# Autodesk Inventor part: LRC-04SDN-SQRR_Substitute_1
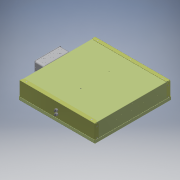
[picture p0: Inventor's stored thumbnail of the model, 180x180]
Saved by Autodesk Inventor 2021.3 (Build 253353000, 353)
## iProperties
Part Number: LRC-04SDN-SQRR_Substitute_1
Material: Generic
Document SubType Name: Modeling
Designer: JChurch
Manufacturer: Standard
Standards Organization: Custom
Density: 1 g/cm^3
Appearance: Smooth - Black
Author: JChurch
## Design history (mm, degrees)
derived "LRC-04SDN-SQRR.iam"
body "Solid9"
node "830557-00-00.iam:1::830557-PAN.ipt:1"
node "830557-00-00.iam:1::830557-FLANGE.ipt:2"
body "Solid10"
node "830557-00-00.iam:1::506010-00-38 SQUEEZED.ipt:1"
body "Solid11"
node "830557-00-00.iam:1::506010-00-38 SQUEEZED.ipt:2"
body "Solid12"
node "830557-00-00.iam:1::506010-00-38 SQUEEZED.ipt:3"
body "Solid13"
node "830557-00-00.iam:1::506010-00-38 SQUEEZED.ipt:4"
body "Solid14"
node "830557-00-00.iam:1::506010-00-38 SQUEEZED.ipt:5"
body "Solid15"
node "830557-00-00.iam:1::506010-00-38 SQUEEZED.ipt:6"
body "Solid16"
node "830557-00-00.iam:1::506010-00-38 SQUEEZED.ipt:7"
body "Solid17"
node "830557-00-00.iam:1::506010-00-38 SQUEEZED.ipt:8"
body "Solid18"
node "830557-00-00.iam:1::830557-FLANGE.ipt:3"
body "Solid19"
node "885000-00-00.iam:1::830000-00-00.ipt:1"
body "Solid20"
node "885000-00-00.iam:1::509424-00-00.ipt:1"
body "Solid21"
node "885000-00-00.iam:1::830593-00-00.ipt:1"
body "Solid22"
node "885000-00-00.iam:1::506002-00-00.ipt:1"
body "Solid23"
node "885000-00-00.iam:1::506002-00-00.ipt:2"
body "Solid24"
node "885000-00-00.iam:1::506002-00-00.ipt:3"
body "Solid25"
node "885000-00-00.iam:1::506002-00-00.ipt:4"
body "Solid26"
node "885000-00-00.iam:1::506002-00-00.ipt:5"
body "Solid27"
node "885000-00-00.iam:1::506002-00-00.ipt:6"
body "Solid28"
node "885000-00-00.iam:1::506002-00-00.ipt:7"
body "Solid29"
node "885000-00-00.iam:1::506002-00-00.ipt:8"
body "Solid30"
node "885000-00-00.iam:1::506002-00-00.ipt:9"
body "Solid31"
node "885000-00-00.iam:1::506002-00-00.ipt:10"
body "Solid32"
node "885000-00-00.iam:1::506002-00-00.ipt:11"
body "Solid33"
node "885000-00-00.iam:1::506002-00-00.ipt:12"
body "Solid34"
node "885000-00-00.iam:1::506002-00-00.ipt:13"
body "Solid35"
node "885000-00-00.iam:1::506002-00-00.ipt:14"
body "Solid36"
node "885000-00-00.iam:1::500027-00-00.ipt:1"
body "Solid37"
node "885000-00-00.iam:1::500027-00-00.ipt:2"
body "Solid38"
node "885000-00-00.iam:1::502116-00-00.ipt:1"
body "Solid39"
node "885000-00-00.iam:1::502116-00-00.ipt:2"
body "Solid40"
node "885000-00-00.iam:1::501030-00-00.ipt:1"
body "Solid41"
node "885000-00-00.iam:1::501030-00-00.ipt:2"
body "Solid42"
node "885000-00-00.iam:1::501030-00-00.ipt:3"
body "Solid43"
node "885000-00-00.iam:1::501030-00-00.ipt:4"
body "Solid44"
node "885000-00-00.iam:1::500027-00-00.ipt:3"
body "Solid45"
node "885000-00-00.iam:1::500027-00-00.ipt:4"
body "Solid46"
node "885000-00-00.iam:1::501030-00-00.ipt:5"
body "Solid47"
node "885000-00-00.iam:1::500027-00-00.ipt:5"
body "Solid48"
node "885000-00-00.iam:1::501030-00-00.ipt:6"
body "Solid49"
node "885000-00-00.iam:1::500027-00-00.ipt:6"
body "Solid50"
node "885000-00-00.iam:1::830593-00-00.ipt:2"
body "Solid51"
node "885000-00-00.iam:1::507032-00-00.ipt:1"
body "Solid52"
node "885000-00-00.iam:1::640042-00-03.ipt:1"
body "Solid53"
node "885000-00-00.iam:1::501030-00-00.ipt:9"
body "Solid54"
node "885000-00-00.iam:1::501030-00-00.ipt:10"
body "Solid55"
node "885000-00-00.iam:1::501030-00-00.ipt:11"
body "Solid56"
node "885000-00-00.iam:1::501030-00-00.ipt:12"
body "Solid57"
node "885000-00-00.iam:1::503031-00-00.ipt:1"
body "Solid58"
node "885000-00-00.iam:1::503031-00-00.ipt:2"
body "Solid59"
node "885000-00-00.iam:1::509425-00-00.ipt:1"
body "Solid60"
node "750206-00-00.iam:1::740066-00-XX.iam:1::840076-00-00_5.75.ip"
body "Solid61"
node "750206-00-00.iam:1::740066-00-XX.iam:1::840076-00-00_5.75.ip"
body "Solid62"
node "750206-00-00.iam:1::740066-00-XX.iam:1::840076-00-00_5.75.ip"
body "Solid63"
node "750206-00-00.iam:1::740066-00-XX.iam:1::840076-00-00_5.75.ip"
body "Solid64"
node "750206-00-00.iam:1::507055-00-38.ipt:1"
body "Solid65"
node "750206-00-00.iam:1::507055-00-38.ipt:2"
body "Solid66"
node "725292-00-00.ipt:1"
body "Solid67"
other parameters: "d15" = 61.595, "d16" = 9.525, "d17" = 9.525, "d35" = 5.08
